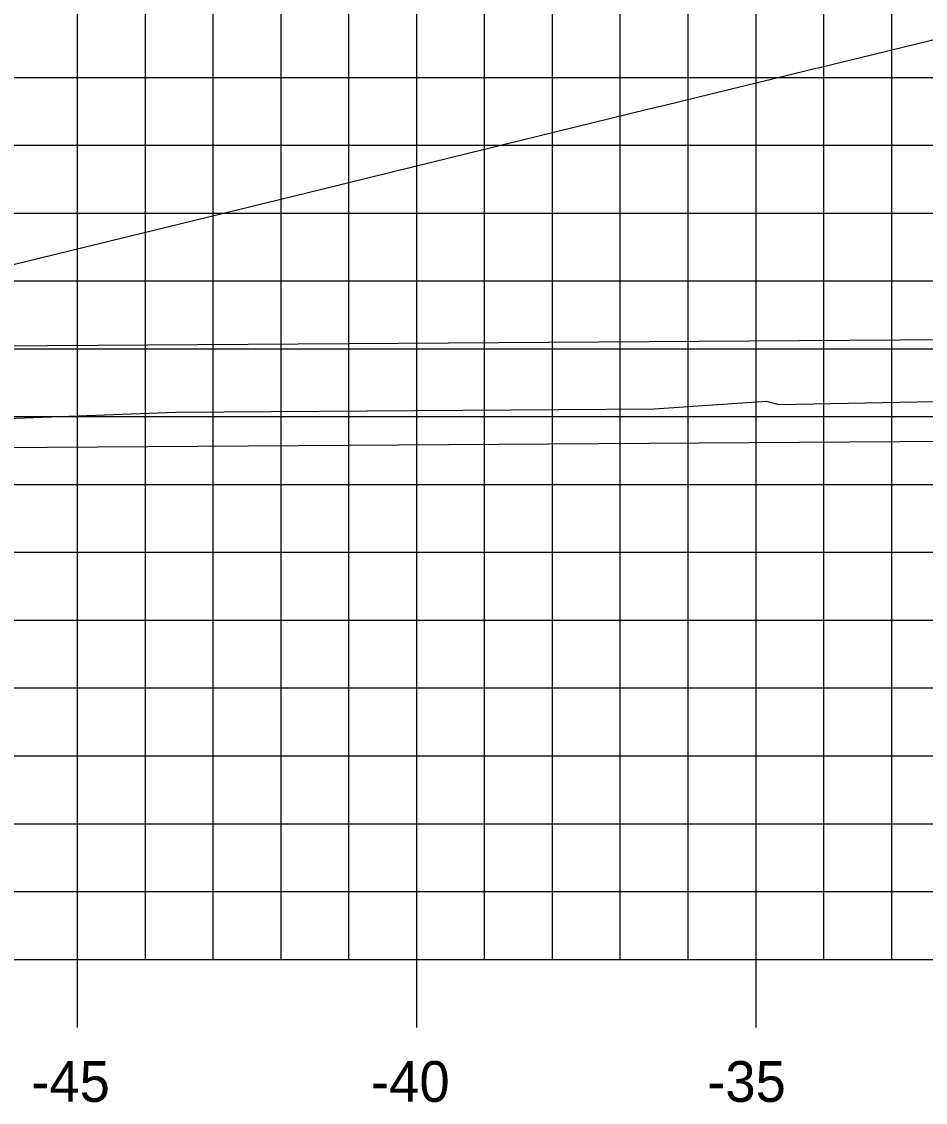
# Model space of a CAD drawing. Extents: x 851639 to 851810, y 365876 to 365986.
# Drawn here: x 851675.83 to 851689.15, y 365912.72 to 365928.66 of the extents above; entities that cross this region are included whole.
import ezdxf

# ---------------------------------------------------------------- set-up
doc = ezdxf.new("R2010")
doc.units = 0
for name, color, linetype in [('D_Drainage_Culvert', 7, 'Continuous'), ('D_Roadway_Centerline', 7, 'Continuous'), ('H_V ANNOTATION', 7, 'Continuous'), ('MAJOR', 7, 'Continuous'), ('MINOR', 7, 'Continuous'), ('S_Roadway_Centerline', 7, 'Continuous')]:
    doc.layers.add(name, color=color, linetype=linetype)

msp = doc.modelspace()

# ---------------------------------------------------------------- linework, layer by layer
at = {"layer": 'D_Drainage_Culvert'}
for p, q in [((851741.273, 365924.315), (851669.281, 365923.829)), ((851741.289, 365922.815), (851669.291, 365922.329))]:
    msp.add_line(p, q, dxfattribs=at)
at = {"layer": 'D_Roadway_Centerline'}
msp.add_lwpolyline([(851673.892, 365924.629), (851675.204, 365924.951), (851675.42, 365925.004), (851675.685, 365925.069), (851677.762, 365925.578), (851680.256, 365926.188), (851681.613, 365926.521), (851685.056, 365927.363), (851685.313, 365927.426), (851687.4, 365927.936), (851687.536, 365927.969), (851687.569, 365927.977), (851689.622, 365928.478)], dxfattribs=at)
at = {"layer": 'MAJOR'}
for p, q in [((851676.655, 365914.833), (851676.655, 365939.833)), ((851681.655, 365914.833), (851681.655, 365939.833)), ((851686.655, 365914.833), (851686.655, 365939.833)), ((851651.655, 365924.833), (851791.655, 365924.833)), ((851651.655, 365919.833), (851791.655, 365919.833)), ((851651.655, 365914.833), (851791.655, 365914.833)), ((851651.655, 365914.833), (851791.655, 365914.833)), ((851676.655, 365913.831), (851676.655, 365914.833)), ((851681.655, 365913.831), (851681.655, 365914.833)), ((851686.655, 365913.831), (851686.655, 365914.833))]:
    msp.add_line(p, q, dxfattribs=at)
at = {"layer": 'MINOR'}
for p, q in [((851677.655, 365914.833), (851677.655, 365939.833)), ((851678.655, 365914.833), (851678.655, 365939.833)), ((851679.655, 365914.833), (851679.655, 365939.833)), ((851680.655, 365914.833), (851680.655, 365939.833)), ((851682.655, 365914.833), (851682.655, 365939.833)), ((851683.655, 365914.833), (851683.655, 365939.833)), ((851684.655, 365914.833), (851684.655, 365939.833)), ((851685.655, 365914.833), (851685.655, 365939.833)), ((851687.655, 365914.833), (851687.655, 365939.833)), ((851688.655, 365914.833), (851688.655, 365939.833)), ((851651.655, 365927.833), (851791.655, 365927.833)), ((851651.655, 365926.833), (851791.655, 365926.833)), ((851651.655, 365925.833), (851791.655, 365925.833)), ((851651.655, 365923.833), (851791.655, 365923.833)), ((851651.655, 365922.833), (851791.655, 365922.833)), ((851651.655, 365921.833), (851791.655, 365921.833)), ((851651.655, 365920.833), (851791.655, 365920.833)), ((851651.655, 365918.833), (851791.655, 365918.833)), ((851651.655, 365917.833), (851791.655, 365917.833)), ((851651.655, 365916.833), (851791.655, 365916.833)), ((851651.655, 365915.833), (851791.655, 365915.833))]:
    msp.add_line(p, q, dxfattribs=at)
at = {"layer": 'S_Roadway_Centerline'}
msp.add_lwpolyline([(851651.655, 365922.491), (851651.949, 365922.492), (851651.993, 365922.485), (851652.16, 365922.501), (851655.843, 365922.751), (851658.065, 365922.756), (851658.171, 365922.691), (851662.127, 365922.37), (851663.756, 365922.395), (851664.788, 365922.378), (851664.934, 365922.24), (851667.544, 365922.499), (851674.034, 365922.745), (851678.105, 365922.897), (851685.154, 365922.948), (851686.808, 365923.06), (851686.992, 365923.011), (851693.639, 365923.14)], dxfattribs=at)

# ---------------------------------------------------------------- texts
at = {"layer": 'H_V ANNOTATION'}
for s, p in [('-45', (851675.973, 365912.733)), ('-40', (851680.981, 365912.733)), ('-35', (851685.935, 365912.733))]:
    msp.add_text(s, height=0.6, dxfattribs=at).set_placement(p)

doc.saveas('drawing.dxf')
